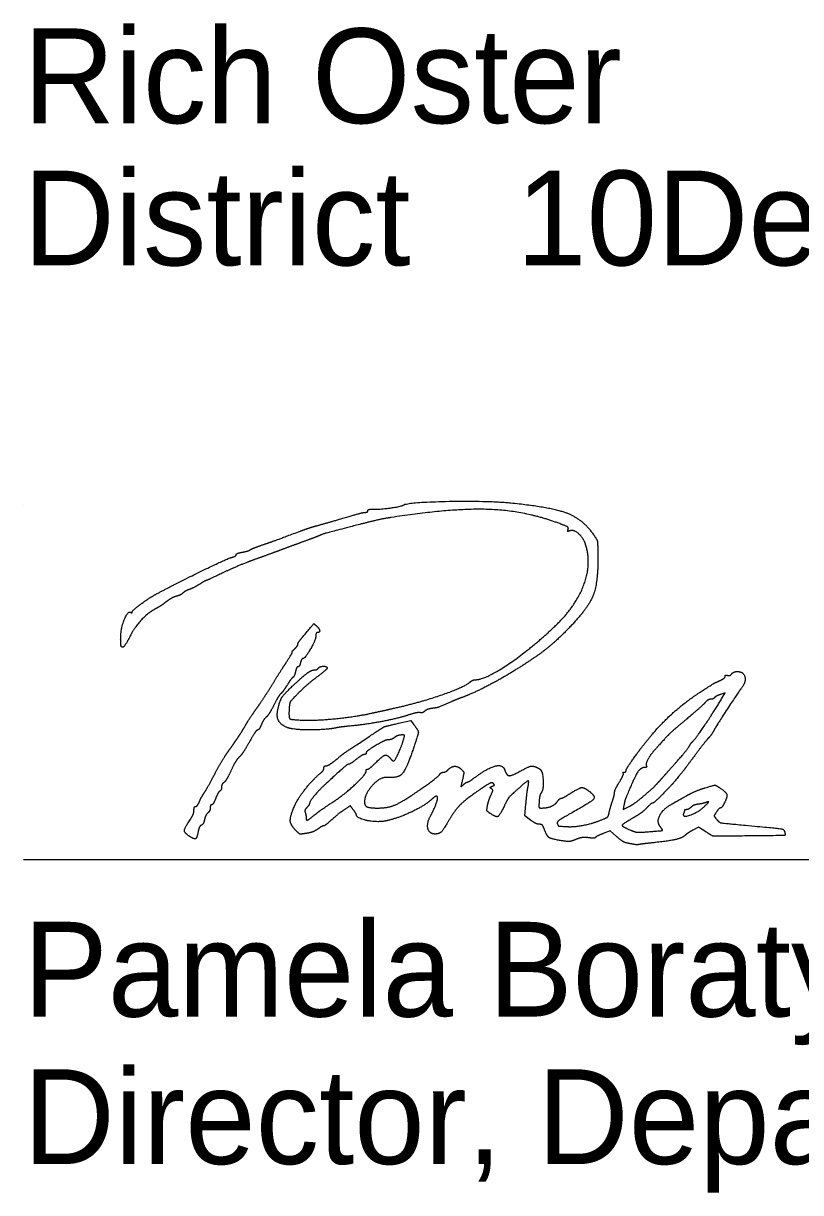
# Model space of a CAD drawing. Extents: x -2.1 to 31.9, y 6.3 to 28.3.
# Drawn here: x 22.462 to 23.611, y 13.45 to 15.178 of the extents above; entities that cross this region are included whole.
import ezdxf

# ---------------------------------------------------------------- set-up
doc = ezdxf.new("R2010")
doc.units = 0
for name, color, linetype in [('SH_Data', 7, 'Continuous'), ('SH_Text', 7, 'Continuous'), ('TX_P_1', 7, 'Continuous')]:
    doc.layers.add(name, color=color, linetype=linetype)

msp = doc.modelspace()

# ---------------------------------------------------------------- linework, layer by layer
at = {"layer": 'SH_Data'}
for p, q in [((22.4623, 14.4648), (22.4623, 14.4648)), ((22.4623, 13.9426), (25.9623, 13.9426))]:
    msp.add_line(p, q, dxfattribs=at)
at = {"layer": 'TX_P_1'}
for points in [[(23.4941, 14.1798), (23.4995, 14.1887), (23.4922, 14.1862)], [(23.0168, 14.1437), (23.0348, 14.1477), (23.0395, 14.1415)], [(23.2118, 14.0008), (23.2034, 14.0072), (23.2049, 14.0242)], [(23.3498, 14.0228), (23.3487, 14.0164), (23.3574, 14.0208)], [(23.3387, 13.9765), (23.3295, 13.9848), (23.319, 13.9807)], [(23.4706, 13.9835), (23.4599, 13.9903), (23.4516, 13.9858)]]:
    msp.add_lwpolyline(points, dxfattribs=at)
for points in [[(22.9675, 14.4553), (22.9695, 14.4553), (22.9712, 14.4564), (22.9712, 14.4578)], [(22.9712, 14.4578), (22.9712, 14.4592), (22.9753, 14.4602), (22.9802, 14.46)], [(22.9802, 14.46), (22.9898, 14.4597), (23.0208, 14.4641), (23.0242, 14.4662)], [(23.2549, 14.4386), (23.2044, 14.4576), (23.0964, 14.4616), (23.006, 14.4478)], [(23.0242, 14.4662), (23.031, 14.4704), (23.148, 14.4727), (23.1824, 14.4693)], [(23.1824, 14.4693), (23.2417, 14.4635), (23.2892, 14.4452), (23.305, 14.4221)], [(22.8956, 14.4355), (22.9009, 14.4369), (22.9184, 14.4419), (22.9345, 14.4466)], [(22.9345, 14.4466), (22.9506, 14.4514), (22.9654, 14.4553), (22.9675, 14.4553)], [(23.006, 14.4478), (22.9968, 14.4464), (22.9768, 14.442), (22.9616, 14.4381)], [(22.8152, 14.4071), (22.8299, 14.4122), (22.8364, 14.4145), (22.8716, 14.4277)], [(22.8716, 14.4277), (22.8795, 14.4306), (22.8903, 14.4341), (22.8956, 14.4355)], [(22.9616, 14.4381), (22.9106, 14.4249), (22.9063, 14.4237), (22.8956, 14.4193)], [(23.2672, 14.4299), (23.2682, 14.4325), (23.2648, 14.4349), (23.2549, 14.4386)], [(23.2696, 14.4279), (23.267, 14.4269), (23.2663, 14.4275), (23.2672, 14.4299)], [(23.293, 14.408), (23.2898, 14.4177), (23.2753, 14.4301), (23.2696, 14.4279)], [(22.7972, 14.3999), (22.7985, 14.4009), (22.8066, 14.4041), (22.8152, 14.4071)], [(22.8728, 14.4108), (22.8629, 14.4072), (22.8478, 14.4016), (22.8392, 14.3984)], [(22.8956, 14.4193), (22.893, 14.4182), (22.8827, 14.4144), (22.8728, 14.4108)], [(23.2475, 14.2868), (23.2785, 14.3162), (23.3023, 14.3797), (23.293, 14.408)], [(23.305, 14.4221), (23.31, 14.4149), (23.3109, 14.4106), (23.3112, 14.3927)], [(22.6592, 14.3349), (22.6894, 14.3511), (22.763, 14.3868), (22.7714, 14.3892)], [(22.7714, 14.3892), (22.7744, 14.3901), (22.7768, 14.3917), (22.7768, 14.3928)], [(22.7768, 14.3928), (22.7768, 14.3939), (22.7809, 14.3955), (22.7858, 14.3964)], [(22.7858, 14.3964), (22.7908, 14.3974), (22.7959, 14.3989), (22.7972, 14.3999)], [(22.8392, 14.3984), (22.8306, 14.3952), (22.8144, 14.3893), (22.8032, 14.3853)], [(23.3112, 14.3927), (23.312, 14.3519), (23.2959, 14.3122), (23.2664, 14.2823)], [(22.8032, 14.3853), (22.792, 14.3813), (22.7716, 14.3727), (22.758, 14.3663)], [(22.7321, 14.3545), (22.7316, 14.3545), (22.7271, 14.352), (22.7222, 14.3488)], [(22.758, 14.3663), (22.7443, 14.3598), (22.7327, 14.3545), (22.7321, 14.3545)], [(22.7073, 14.3413), (22.7041, 14.3403), (22.7, 14.338), (22.6982, 14.3362)], [(22.7222, 14.3488), (22.7172, 14.3457), (22.7106, 14.3424), (22.7073, 14.3413)], [(22.6232, 14.3083), (22.6232, 14.3104), (22.6486, 14.3292), (22.6592, 14.3349)], [(22.6736, 14.3233), (22.669, 14.3197), (22.6619, 14.315), (22.6577, 14.3129)], [(22.6885, 14.3313), (22.6849, 14.3305), (22.6782, 14.3268), (22.6736, 14.3233)], [(22.6982, 14.3362), (22.6964, 14.3344), (22.692, 14.3322), (22.6885, 14.3313)], [(22.6061, 14.2704), (22.6062, 14.2836), (22.6168, 14.3102), (22.6209, 14.3076)], [(22.6209, 14.3076), (22.6222, 14.3068), (22.6232, 14.3071), (22.6232, 14.3083)], [(22.6577, 14.3129), (22.6473, 14.3076), (22.6274, 14.2867), (22.6212, 14.2746)], [(22.8734, 14.2693), (22.892, 14.2915), (22.8913, 14.2909), (22.8954, 14.2875)], [(22.8954, 14.2875), (22.8996, 14.284), (22.9006, 14.2777), (22.8968, 14.2777)], [(23.1308, 14.2081), (23.1449, 14.2081), (23.213, 14.254), (23.2475, 14.2868)], [(22.6074, 14.2567), (22.6066, 14.2575), (22.606, 14.2637), (22.6061, 14.2704)], [(22.6212, 14.2746), (22.6146, 14.2617), (22.6093, 14.2548), (22.6074, 14.2567)], [(22.868, 14.2607), (22.868, 14.2619), (22.8705, 14.2658), (22.8734, 14.2693)], [(22.8944, 14.2726), (22.8944, 14.2671), (22.8785, 14.2393), (22.8753, 14.2393)], [(22.8968, 14.2777), (22.8955, 14.2777), (22.8944, 14.2754), (22.8944, 14.2726)], [(23.2664, 14.2823), (23.2479, 14.2634), (23.2154, 14.2385), (23.185, 14.2197)], [(22.8595, 14.2489), (22.8589, 14.2489), (22.8606, 14.2511), (22.8632, 14.2537)], [(22.8632, 14.2537), (22.8659, 14.2563), (22.868, 14.2595), (22.868, 14.2607)], [(22.8284, 14.1982), (22.835, 14.2089), (22.8449, 14.2246), (22.8505, 14.2332)], [(22.8505, 14.2332), (22.856, 14.2418), (22.8601, 14.2489), (22.8595, 14.2489)], [(22.8718, 14.2333), (22.871, 14.23), (22.8694, 14.2273), (22.8682, 14.2273)], [(22.8753, 14.2393), (22.8742, 14.2393), (22.8727, 14.2366), (22.8718, 14.2333)], [(22.8596, 14.1983), (22.8753, 14.213), (22.8881, 14.2225), (22.892, 14.2225)], [(22.8644, 14.2201), (22.8636, 14.2162), (22.8618, 14.2123), (22.8605, 14.2115)], [(22.8682, 14.2273), (22.867, 14.2273), (22.8653, 14.2241), (22.8644, 14.2201)], [(22.892, 14.2225), (22.8945, 14.2225), (22.8972, 14.2236), (22.898, 14.2249)], [(22.9112, 14.2253), (22.9112, 14.2242), (22.9045, 14.2182), (22.8962, 14.2121)], [(22.898, 14.2249), (22.8998, 14.2278), (22.9112, 14.2281), (22.9112, 14.2253)], [(23.185, 14.2197), (23.1658, 14.2078), (23.1245, 14.1869), (23.1104, 14.1818)], [(23.5026, 14.2145), (23.5045, 14.2138), (23.5074, 14.2147), (23.5089, 14.2166)], [(23.5089, 14.2166), (23.5105, 14.2185), (23.5142, 14.2201), (23.5171, 14.2201)], [(23.5171, 14.2201), (23.5266, 14.2201), (23.5303, 14.204), (23.5229, 14.1951)], [(22.8383, 14.1637), (22.841, 14.1767), (22.8472, 14.1867), (22.8596, 14.1983)], [(22.8521, 14.2001), (22.8487, 14.1946), (22.8445, 14.189), (22.8429, 14.1877)], [(22.8605, 14.2115), (22.8593, 14.2107), (22.8555, 14.2056), (22.8521, 14.2001)], [(22.8962, 14.2121), (22.888, 14.206), (22.8755, 14.1952), (22.8684, 14.188)], [(23.0108, 14.1662), (23.0478, 14.1744), (23.114, 14.1972), (23.1226, 14.2048)], [(23.1226, 14.2048), (23.1247, 14.2066), (23.1284, 14.2081), (23.1308, 14.2081)], [(23.4624, 14.1897), (23.4814, 14.202), (23.4832, 14.203), (23.4914, 14.2067)], [(23.4914, 14.2067), (23.4957, 14.2087), (23.4992, 14.2115), (23.4992, 14.213)], [(23.4992, 14.213), (23.4992, 14.2146), (23.5008, 14.2152), (23.5026, 14.2145)], [(22.8067, 14.1653), (22.812, 14.1728), (22.8218, 14.1876), (22.8284, 14.1982)], [(22.8429, 14.1877), (22.8412, 14.1863), (22.8366, 14.1787), (22.8325, 14.1707)], [(22.8684, 14.188), (22.8577, 14.1771), (22.8555, 14.1734), (22.855, 14.1652)], [(23.1104, 14.1818), (23.1058, 14.1801), (23.0988, 14.1773), (23.0948, 14.1756)], [(23.3678, 14.0972), (23.3901, 14.128), (23.4351, 14.172), (23.4624, 14.1897)], [(23.4835, 14.1815), (23.4827, 14.1803), (23.4803, 14.1793), (23.4782, 14.1793)], [(23.5229, 14.1951), (23.5188, 14.19), (23.4859, 14.1396), (23.4828, 14.1334)], [(23.4922, 14.1862), (23.4881, 14.1848), (23.4842, 14.1826), (23.4835, 14.1815)], [(22.7899, 14.1397), (22.7938, 14.1463), (22.8013, 14.1578), (22.8067, 14.1653)], [(22.8325, 14.1707), (22.8285, 14.1627), (22.8234, 14.1547), (22.8213, 14.1529)], [(22.855, 14.1652), (22.8542, 14.1517), (22.8582, 14.1488), (22.8788, 14.1483)], [(22.9772, 14.1587), (22.9851, 14.1604), (23.0003, 14.1638), (23.0108, 14.1662)], [(23.0662, 14.1657), (23.0623, 14.1652), (23.0575, 14.1634), (23.0554, 14.1616)], [(23.0948, 14.1756), (23.0777, 14.1681), (23.0728, 14.1664), (23.0662, 14.1657)], [(23.4693, 14.1739), (23.4666, 14.1709), (23.4542, 14.1599), (23.4416, 14.1493)], [(23.4513, 14.1169), (23.4542, 14.1188), (23.4824, 14.1603), (23.4941, 14.1798)], [(23.4782, 14.1793), (23.476, 14.1793), (23.472, 14.1769), (23.4693, 14.1739)], [(22.8213, 14.1529), (22.8191, 14.1511), (22.8158, 14.1461), (22.814, 14.1417)], [(22.8536, 14.1369), (22.8432, 14.1408), (22.8361, 14.1532), (22.8383, 14.1637)], [(22.8788, 14.1483), (22.8981, 14.1478), (22.9559, 14.1539), (22.9772, 14.1587)], [(23.0306, 14.1557), (23.0141, 14.1504), (22.9691, 14.1419), (22.9453, 14.1396)], [(23.0486, 14.1594), (23.047, 14.16), (23.0389, 14.1583), (23.0306, 14.1557)], [(23.0554, 14.1616), (23.0533, 14.1598), (23.0503, 14.1588), (23.0486, 14.1594)], [(23.4416, 14.1493), (23.422, 14.1328), (23.4103, 14.1214), (23.3936, 14.1025)], [(22.7769, 14.1191), (22.7802, 14.1238), (22.7861, 14.1331), (22.7899, 14.1397)], [(22.8083, 14.1337), (22.807, 14.1337), (22.8016, 14.1258), (22.7963, 14.1161)], [(22.814, 14.1417), (22.8122, 14.1373), (22.8096, 14.1337), (22.8083, 14.1337)], [(22.9249, 14.137), (22.9111, 14.134), (22.8617, 14.1339), (22.8536, 14.1369)], [(22.9453, 14.1396), (22.9369, 14.1388), (22.9277, 14.1376), (22.9249, 14.137)], [(22.9628, 14.1172), (22.9945, 14.1383), (22.9959, 14.1389), (23.0168, 14.1437)], [(23.0395, 14.1415), (23.0461, 14.1328), (23.0459, 14.1279), (23.0382, 14.1053)], [(23.4828, 14.1334), (23.481, 14.13), (23.4771, 14.1245), (23.4741, 14.1213)], [(22.7634, 14.0999), (22.7675, 14.1057), (22.7736, 14.1143), (22.7769, 14.1191)], [(22.7963, 14.1161), (22.7909, 14.1065), (22.7842, 14.0965), (22.7814, 14.0939)], [(22.9236, 14.0893), (22.9373, 14.1004), (22.9354, 14.099), (22.9628, 14.1172)], [(22.9925, 14.1162), (22.9781, 14.1082), (22.9688, 14.1018), (22.9688, 14.0999)], [(23.0022, 14.1193), (23, 14.1193), (22.9956, 14.1179), (22.9925, 14.1162)], [(23.011, 14.1228), (23.0084, 14.1209), (23.0045, 14.1193), (23.0022, 14.1193)], [(23.0095, 14.0881), (23.0113, 14.0881), (23.021, 14.1092), (23.0242, 14.1199)], [(23.0209, 14.1264), (23.018, 14.1264), (23.0135, 14.1248), (23.011, 14.1228)], [(23.0242, 14.1199), (23.0258, 14.1257), (23.0254, 14.1265), (23.0209, 14.1264)], [(23.4474, 14.1118), (23.4486, 14.1139), (23.4504, 14.1162), (23.4513, 14.1169)], [(23.4741, 14.1213), (23.4711, 14.1181), (23.4622, 14.1067), (23.4543, 14.0961)], [(22.7445, 14.0677), (22.7508, 14.0796), (22.7593, 14.094), (22.7634, 14.0999)], [(22.9662, 14.0977), (22.9647, 14.0977), (22.9594, 14.0945), (22.9544, 14.0905)], [(22.9688, 14.0999), (22.9688, 14.0987), (22.9676, 14.0977), (22.9662, 14.0977)], [(22.9832, 14.0857), (22.9934, 14.0958), (22.9999, 14.0976), (23.0048, 14.0917)], [(23.0382, 14.1053), (23.028, 14.0754), (23.016, 14.0624), (23, 14.0637)], [(23.3528, 14.0739), (23.3528, 14.0753), (23.3596, 14.0858), (23.3678, 14.0972)], [(23.3936, 14.1025), (23.3878, 14.0959), (23.3815, 14.083), (23.383, 14.0807)], [(23.4161, 14.0739), (23.4315, 14.0911), (23.445, 14.1074), (23.4474, 14.1118)], [(23.4543, 14.0961), (23.4464, 14.0854), (23.4388, 14.0752), (23.4373, 14.0734)], [(22.7814, 14.0939), (22.7786, 14.0914), (22.773, 14.0823), (22.7691, 14.0737)], [(22.901, 14.0697), (22.904, 14.0721), (22.9064, 14.0756), (22.9064, 14.0775)], [(22.9064, 14.0775), (22.9064, 14.0794), (22.9079, 14.0809), (22.9098, 14.0809)], [(22.9433, 14.0833), (22.9414, 14.0833), (22.9329, 14.076), (22.9076, 14.0528)], [(22.9098, 14.0809), (22.9116, 14.0809), (22.9179, 14.0847), (22.9236, 14.0893)], [(22.9544, 14.0905), (22.9494, 14.0865), (22.9444, 14.0833), (22.9433, 14.0833)], [(22.9712, 14.0761), (22.9725, 14.0761), (22.9779, 14.0804), (22.9832, 14.0857)], [(23.0048, 14.0917), (23.0065, 14.0897), (23.0086, 14.0881), (23.0095, 14.0881)], [(23.09, 14.0752), (23.0949, 14.0802), (23.1049, 14.0802), (23.1099, 14.0753)], [(23.128, 14.0626), (23.1482, 14.0778), (23.1709, 14.0834), (23.1739, 14.074)], [(23.1977, 14.0736), (23.2097, 14.0802), (23.2169, 14.0809), (23.2251, 14.0763)], [(23.3807, 14.0785), (23.3744, 14.0785), (23.3648, 14.0633), (23.3528, 14.0341)], [(23.383, 14.0807), (23.3837, 14.0795), (23.3827, 14.0785), (23.3807, 14.0785)], [(22.729, 14.0401), (22.7312, 14.0434), (22.7382, 14.0558), (22.7445, 14.0677)], [(22.7691, 14.0737), (22.7652, 14.0651), (22.7604, 14.0572), (22.7586, 14.0562)], [(22.8629, 14.0214), (22.8674, 14.0319), (22.8906, 14.0613), (22.901, 14.0697)], [(22.9228, 14.0295), (22.9383, 14.0399), (22.9688, 14.0687), (22.9688, 14.073)], [(23, 14.0637), (22.9896, 14.0646), (22.9664, 14.0392), (22.9664, 14.027)], [(22.9688, 14.073), (22.9688, 14.0747), (22.9699, 14.0761), (22.9712, 14.0761)], [(23.0348, 14.0364), (23.0534, 14.0488), (23.0758, 14.0655), (23.0775, 14.0682)], [(23.0775, 14.0682), (23.0786, 14.0699), (23.0809, 14.0713), (23.0828, 14.0713)], [(23.0828, 14.0713), (23.0846, 14.0713), (23.0878, 14.073), (23.09, 14.0752)], [(23.1112, 14.0605), (23.1088, 14.0502), (23.1089, 14.0498), (23.1127, 14.0532)], [(23.1099, 14.0753), (23.113, 14.0721), (23.1132, 14.0696), (23.1112, 14.0605)], [(23.1186, 14.0569), (23.1195, 14.0569), (23.1238, 14.0595), (23.128, 14.0626)], [(23.1739, 14.074), (23.1763, 14.0664), (23.1844, 14.0662), (23.1977, 14.0736)], [(23.2251, 14.0763), (23.2295, 14.0739), (23.2312, 14.0459), (23.2273, 14.0407)], [(23.3431, 14.057), (23.3469, 14.0633), (23.3494, 14.0691), (23.3487, 14.0699)], [(23.3487, 14.0699), (23.3479, 14.0706), (23.3485, 14.0713), (23.35, 14.0713)], [(23.35, 14.0713), (23.3516, 14.0713), (23.3528, 14.0725), (23.3528, 14.0739)], [(23.4005, 14.0565), (23.4037, 14.06), (23.4107, 14.0679), (23.4161, 14.0739)], [(23.4373, 14.0734), (23.424, 14.057), (23.4195, 14.0518), (23.4076, 14.0396)], [(22.7527, 14.0436), (22.7513, 14.0428), (22.7485, 14.0379), (22.7465, 14.0327)], [(22.7552, 14.0497), (22.7552, 14.0472), (22.7541, 14.0445), (22.7527, 14.0436)], [(22.7586, 14.0562), (22.7567, 14.0551), (22.7552, 14.0522), (22.7552, 14.0497)], [(22.9076, 14.0528), (22.8985, 14.0444), (22.8848, 14.0273), (22.8848, 14.0243)], [(23.1365, 14.0454), (23.1167, 14.0319), (23.0995, 14.0149), (23.0912, 14.0005)], [(23.1127, 14.0532), (23.115, 14.0552), (23.1176, 14.0569), (23.1186, 14.0569)], [(23.1567, 14.0548), (23.1549, 14.0566), (23.149, 14.0539), (23.1365, 14.0454)], [(23.1538, 14.0472), (23.1516, 14.0485), (23.1519, 14.0495), (23.155, 14.0506)], [(23.1531, 14.0373), (23.156, 14.0436), (23.1561, 14.0457), (23.1538, 14.0472)], [(23.155, 14.0506), (23.158, 14.0518), (23.1585, 14.053), (23.1567, 14.0548)], [(23.1978, 14.0508), (23.1818, 14.0367), (23.1781, 14.0323), (23.1726, 14.021)], [(23.2079, 14.0491), (23.2097, 14.0585), (23.2071, 14.059), (23.1978, 14.0508)], [(23.2049, 14.0242), (23.2057, 14.0336), (23.207, 14.0448), (23.2079, 14.0491)], [(23.2986, 14.0431), (23.3083, 14.0355), (23.3015, 14.0275), (23.2699, 14.0098)], [(23.2704, 14.0401), (23.2834, 14.0483), (23.2909, 14.0491), (23.2986, 14.0431)], [(23.336, 14.0422), (23.336, 14.0441), (23.3392, 14.0507), (23.3431, 14.057)], [(23.3804, 14.0376), (23.3883, 14.0445), (23.3974, 14.0529), (23.4005, 14.0565)], [(23.4404, 14.0356), (23.4483, 14.0402), (23.4615, 14.0459), (23.4697, 14.0483)], [(23.4697, 14.0483), (23.4838, 14.0525), (23.4849, 14.0526), (23.4908, 14.0487)], [(23.4908, 14.0487), (23.5004, 14.0424), (23.5028, 14.035), (23.4982, 14.026)], [(22.7169, 14.0209), (22.7182, 14.0209), (22.7206, 14.0239), (22.7222, 14.0275)], [(22.7222, 14.0275), (22.7237, 14.0311), (22.7268, 14.0368), (22.729, 14.0401)], [(22.7465, 14.0327), (22.7444, 14.0275), (22.7417, 14.0233), (22.7406, 14.0233)], [(22.8912, 14.0072), (22.8988, 14.0133), (22.904, 14.017), (22.9228, 14.0295)], [(22.9664, 14.027), (22.9664, 14.0218), (22.9742, 14.0185), (22.9864, 14.0185)], [(22.9864, 14.0185), (22.9994, 14.0185), (23.0185, 14.0256), (23.0348, 14.0364)], [(23.0668, 14.0323), (23.0572, 14.0231), (23.0185, 14.0043), (23, 13.9999)], [(23.0638, 14.0065), (23.068, 14.0142), (23.0744, 14.0304), (23.0744, 14.0332)], [(23.0744, 14.0332), (23.0744, 14.0362), (23.0705, 14.0358), (23.0668, 14.0323)], [(23.148, 14.0217), (23.1488, 14.0259), (23.1511, 14.0329), (23.1531, 14.0373)], [(23.2244, 14.0281), (23.2239, 14.0205), (23.2246, 14.0185), (23.2277, 14.0185)], [(23.2273, 14.0407), (23.226, 14.039), (23.2247, 14.0334), (23.2244, 14.0281)], [(23.2277, 14.0185), (23.236, 14.0185), (23.248, 14.0233), (23.2513, 14.028)], [(23.2513, 14.028), (23.2532, 14.0307), (23.2557, 14.0329), (23.2569, 14.0329)], [(23.2569, 14.0329), (23.2581, 14.0329), (23.2642, 14.0361), (23.2704, 14.0401)], [(23.3277, 14.011), (23.3284, 14.0145), (23.3306, 14.0222), (23.3325, 14.0281)], [(23.3325, 14.0281), (23.3345, 14.034), (23.336, 14.0404), (23.336, 14.0422)], [(23.3528, 14.0341), (23.3517, 14.0315), (23.3503, 14.0264), (23.3498, 14.0228)], [(23.3574, 14.0208), (23.3621, 14.0232), (23.3725, 14.0308), (23.3804, 14.0376)], [(23.392, 14.0257), (23.3909, 14.0257), (23.3871, 14.0226), (23.3834, 14.0187)], [(23.4076, 14.0396), (23.4001, 14.032), (23.3931, 14.0257), (23.392, 14.0257)], [(23.4209, 14.0246), (23.4237, 14.0262), (23.4325, 14.0311), (23.4404, 14.0356)], [(23.4716, 14.0269), (23.469, 14.026), (23.4637, 14.0247), (23.4598, 14.0242)], [(23.4692, 14.0214), (23.4747, 14.027), (23.4753, 14.0283), (23.4716, 14.0269)], [(23.4982, 14.026), (23.496, 14.0219), (23.4934, 14.0185), (23.4922, 14.0185)], [(22.7086, 14.001), (22.7118, 14.0057), (22.7144, 14.0121), (22.7144, 14.0152)], [(22.7144, 14.0152), (22.7144, 14.0183), (22.7155, 14.0209), (22.7169, 14.0209)], [(22.735, 14.0114), (22.7331, 14.0098), (22.7308, 14.0053), (22.7299, 14.0014)], [(22.7384, 14.0188), (22.7384, 14.0163), (22.7369, 14.013), (22.735, 14.0114)], [(22.7406, 14.0233), (22.7394, 14.0233), (22.7384, 14.0213), (22.7384, 14.0188)], [(22.8646, 13.9857), (22.857, 13.9933), (22.8564, 14.0061), (22.8629, 14.0214)], [(22.8811, 14.0192), (22.879, 14.0172), (22.8779, 14.0139), (22.8787, 14.012)], [(22.8787, 14.012), (22.8794, 14.0101), (22.88, 14.007), (22.88, 14.0051)], [(22.8848, 14.0243), (22.8848, 14.0236), (22.8831, 14.0213), (22.8811, 14.0192)], [(22.9385, 14.0173), (22.9303, 14.0119), (22.9278, 14.0099), (22.9165, 13.9999)], [(22.9498, 14.0159), (22.9454, 14.0217), (22.9453, 14.0218), (22.9385, 14.0173)], [(22.9544, 14.0086), (22.9543, 14.0094), (22.9523, 14.0127), (22.9498, 14.0159)], [(23, 13.9999), (22.9872, 13.9968), (22.9546, 14.003), (22.9544, 14.0086)], [(23.1526, 14.0102), (23.1477, 14.0134), (23.1469, 14.0154), (23.148, 14.0217)], [(23.1726, 14.021), (23.1659, 14.0073), (23.1611, 14.0046), (23.1526, 14.0102)], [(23.2699, 14.0098), (23.2566, 14.0024), (23.2504, 13.9976), (23.2513, 13.9954)], [(23.3151, 14.0004), (23.3239, 14.0038), (23.3268, 14.0062), (23.3277, 14.011)], [(23.3834, 14.0187), (23.3798, 14.0149), (23.3717, 14.0088), (23.3654, 14.0051)], [(23.4038, 13.9902), (23.3977, 13.9977), (23.4075, 14.0174), (23.4209, 14.0246)], [(23.4378, 14.0104), (23.4353, 14.0038), (23.4608, 14.0128), (23.4692, 14.0214)], [(23.4392, 14.0151), (23.4392, 14.0145), (23.4386, 14.0124), (23.4378, 14.0104)], [(23.442, 14.0161), (23.4405, 14.0161), (23.4392, 14.0156), (23.4392, 14.0151)], [(23.4488, 14.0197), (23.4466, 14.0177), (23.4436, 14.0161), (23.442, 14.0161)], [(23.4598, 14.0242), (23.456, 14.0237), (23.451, 14.0217), (23.4488, 14.0197)], [(23.4864, 14.0127), (23.4829, 14.0073), (23.4829, 14.0065), (23.4867, 14.0017)], [(23.4922, 14.0185), (23.4911, 14.0185), (23.4885, 14.0159), (23.4864, 14.0127)], [(22.7069, 13.9773), (22.6999, 13.9822), (22.7004, 13.9889), (22.7086, 14.001)], [(22.7252, 13.993), (22.7235, 13.9923), (22.7214, 13.9882), (22.7206, 13.9838)], [(22.7299, 14.0014), (22.7291, 13.9974), (22.727, 13.9936), (22.7252, 13.993)], [(22.88, 14.0051), (22.88, 14.0002), (22.8834, 14.0009), (22.8912, 14.0072)], [(22.9058, 13.9921), (22.9047, 13.9921), (22.9009, 13.99), (22.8973, 13.9874)], [(22.9165, 13.9999), (22.9117, 13.9956), (22.9069, 13.9921), (22.9058, 13.9921)], [(23.0706, 13.9801), (23.0622, 13.9801), (23.0581, 13.9959), (23.0638, 14.0065)], [(23.0912, 14.0005), (23.083, 13.9864), (23.0767, 13.9801), (23.0706, 13.9801)], [(23.2248, 13.9945), (23.2222, 13.9945), (23.2163, 13.9973), (23.2118, 14.0008)], [(23.2323, 13.9867), (23.2304, 13.9919), (23.2279, 13.9945), (23.2248, 13.9945)], [(23.2513, 13.9954), (23.2526, 13.992), (23.2533, 13.9918), (23.2652, 13.9911)], [(23.2652, 13.9911), (23.2757, 13.9904), (23.3019, 13.9953), (23.3151, 14.0004)], [(23.3654, 14.0051), (23.3475, 13.9947), (23.3465, 13.9914), (23.3594, 13.9859)], [(23.4867, 14.0017), (23.4904, 13.9972), (23.4953, 13.9962), (23.5292, 13.9931)], [(23.5292, 13.9931), (23.5783, 13.9885), (23.5866, 13.987), (23.5875, 13.9822)], [(22.7206, 13.9838), (22.7188, 13.974), (22.7146, 13.972), (22.7069, 13.9773)], [(22.8808, 13.9811), (22.8721, 13.9797), (22.8699, 13.9804), (22.8646, 13.9857)], [(22.8973, 13.9874), (22.8937, 13.9848), (22.8863, 13.9819), (22.8808, 13.9811)], [(23.2576, 13.9702), (23.2426, 13.9726), (23.2358, 13.977), (23.2323, 13.9867)], [(23.2976, 13.9746), (23.2919, 13.9754), (23.2846, 13.9744), (23.2787, 13.9721)], [(23.3077, 13.975), (23.3073, 13.9741), (23.3028, 13.9739), (23.2976, 13.9746)], [(23.319, 13.9807), (23.3132, 13.9785), (23.3081, 13.9759), (23.3077, 13.975)], [(23.3534, 13.967), (23.3504, 13.9677), (23.3438, 13.9719), (23.3387, 13.9765)], [(23.3594, 13.9859), (23.3663, 13.983), (23.3727, 13.9824), (23.3862, 13.9835)], [(23.3862, 13.9835), (23.4058, 13.985), (23.4075, 13.9857), (23.4038, 13.9902)], [(23.4398, 13.978), (23.4361, 13.9742), (23.4146, 13.9694), (23.3912, 13.967)], [(23.4516, 13.9858), (23.4469, 13.9833), (23.4417, 13.9798), (23.4398, 13.978)], [(23.5172, 13.9771), (23.4815, 13.9767), (23.4811, 13.9768), (23.4706, 13.9835)], [(23.5875, 13.9822), (23.5883, 13.978), (23.5864, 13.9778), (23.5172, 13.9771)], [(23.2787, 13.9721), (23.2718, 13.9693), (23.2662, 13.9688), (23.2576, 13.9702)], [(23.3636, 13.9649), (23.361, 13.9654), (23.3564, 13.9664), (23.3534, 13.967)], [(23.372, 13.9646), (23.37, 13.9642), (23.3663, 13.9644), (23.3636, 13.9649)], [(23.3912, 13.967), (23.3826, 13.9661), (23.374, 13.965), (23.372, 13.9646)]]:
    msp.add_open_spline(points, degree=2, dxfattribs=at)

# ---------------------------------------------------------------- texts
at = {"layer": 'SH_Text'}
for s, p in [('Rich Oster', (22.4623, 15.0302)), ('District       Deputy Director', (22.4623, 14.8202)), ('              10', (22.4623, 14.8202)), ('Pamela Boratyn', (22.4623, 13.7104)), ('Director, Department of Transportation', (22.4623, 13.4926))]:
    msp.add_text(s, height=0.14, dxfattribs=at).set_placement(p)

doc.saveas('drawing.dxf')
